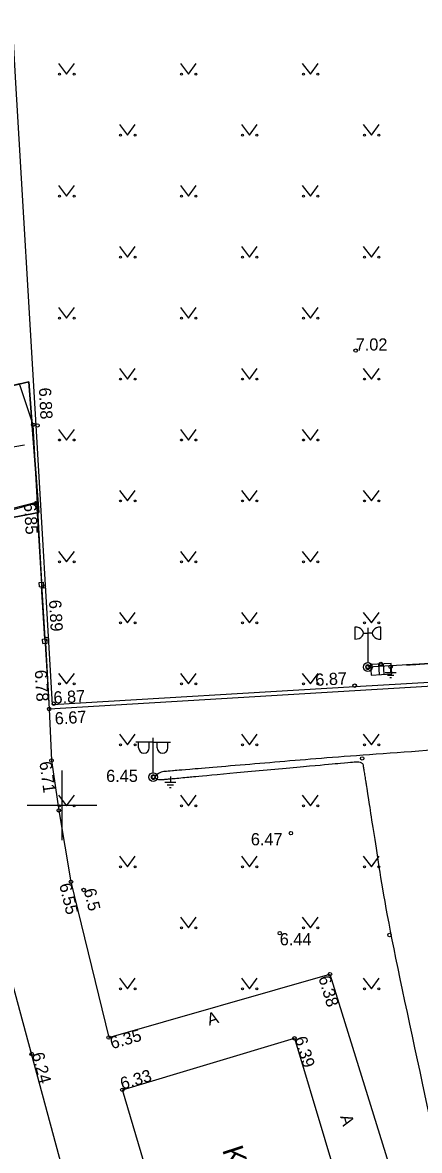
# Model space of a CAD drawing. Extents: x 473307 to 473719, y 6532843 to 6533381.
# Drawn here: x 473397.7 to 473420.5, y 6533180.2 to 6533244.9 of the extents above; entities that cross this region are included whole.
import ezdxf

# ---------------------------------------------------------------- set-up
doc = ezdxf.new("R2010")
doc.units = 0
for name, color, linetype in [('AED', 7, 'Continuous'), ('Default', 7, 'Continuous'), ('HALJASTUS', 7, 'Continuous'), ('HOONE', 7, 'Continuous'), ('KORGUS', 7, 'Continuous'), ('MPKAABEL', 7, 'Continuous'), ('PIIR', 7, 'Continuous'), ('POST', 7, 'Continuous'), ('RELJEEF', 7, 'Continuous'), ('TEE', 7, 'Continuous'), ('VORK', 7, 'Continuous')]:
    doc.layers.add(name, color=color, linetype=linetype)

# ---------------------------------------------------------------- blocks, each defined once
blk = doc.blocks.new('VARPOS')
at = {"layer": 'Default'}
for p, q in [((-0.25, 0.25), (-0.25, -0.25)), ((-0.25, 0.25), (0.25, 0.25)), ((0.25, 0.25), (0.25, -0.25)), ((-0.25, -0.25), (0.25, -0.25))]:
    blk.add_line(p, q, dxfattribs=at)
blk = doc.blocks.new('MEPOST')
at = {"layer": 'Default'}
blk.add_circle((0, 0), 0.5, dxfattribs=at)
for start, end in [(0, 180), (180, 0)]:
    blk.add_arc((0, 0), 0.25, start, end, dxfattribs=at)
blk = doc.blocks.new('VAPOS2')
at = {"layer": 'Default'}
for p, q in [((0, 4), (-2, 4)), ((-1.68, 3.36), (-1.68, 4)), ((-0.45, 3.36), (-0.45, 4)), ((0, 0.5), (0, 4.5)), ((0, 4), (2, 4)), ((0.45, 3.36), (0.45, 4)), ((1.68, 3.36), (1.68, 4))]:
    blk.add_line(p, q, dxfattribs=at)
for centre in [(-1.07, 3.36), (1.07, 3.36)]:
    blk.add_arc(centre, 0.613, 180, 0, dxfattribs=at)
blk = doc.blocks.new('ELKAPP')
at = {"layer": 'Default'}
for p, q in [((1.19, 0.6), (-1.19, 0.6)), ((-1.19, 0.6), (-1.19, -0.6)), ((-0.27, 0.6), (-0.27, -0.6)), ((0.27, 0.6), (0.27, -0.6)), ((1.19, -0.6), (1.19, 0.6)), ((-1.19, -0.6), (1.19, -0.6))]:
    blk.add_line(p, q, dxfattribs=at)
blk = doc.blocks.new('PRMAST')
at = {"layer": 'Default'}
for p, q in [((0, 4.5), (0, 0.5)), ((1.5, 3.19), (1.5, 4.59))]:
    blk.add_line(p, q, dxfattribs=at)
blk.add_lwpolyline([(0.5, 3.89), (0, 3.89)], dxfattribs=at)
blk.add_ellipse((1.5, 3.89), major_axis=(-1, 0), ratio=0.7, start_param=4.712389, end_param=7.853982, dxfattribs=at)
blk = doc.blocks.new('MAANDU')
at = {"layer": 'Default'}
for points in [[(0, 0), (0, -0.68)], [(0.64, -0.68), (-0.64, -0.68)], [(0.37, -0.98), (-0.37, -0.98)], [(0.1, -1.28), (-0.1, -1.28)]]:
    blk.add_lwpolyline(points, dxfattribs=at)
blk = doc.blocks.new('MURU')
at = {"layer": 'Default'}
for p, q in [((-0.93, 1.21), (0, 0)), ((0, 0), (0.89, 1.21))]:
    blk.add_line(p, q, dxfattribs=at)
for centre in [(-0.8, 0), (0.86, 0)]:
    blk.add_circle(centre, 0.11, dxfattribs=at)
blk = doc.blocks.new('VKORIS')
at = {"layer": 'Default'}
for p, q in [((0, 4), (0, -4)), ((-4, 0), (4, 0))]:
    blk.add_line(p, q, dxfattribs=at)

msp = doc.modelspace()

# ---------------------------------------------------------------- linework, layer by layer
at = {"layer": 'AED'}
for points in [[(473398.857, 6533212.804), (473398.35, 6533221.842), (473397.567, 6533224.199), (473383.137, 6533220.726)], [(473398.599, 6533217.405), (473385.116, 6533213.953)], [(473399.015, 6533209.548), (473398.836, 6533212.552)], [(473399.054, 6533209.3), (473399.274, 6533205.529), (473448.417, 6533208.478)]]:
    msp.add_lwpolyline(points, dxfattribs=at)
at = {"layer": 'HOONE'}
msp.add_lwpolyline([(473403.472, 6533183.664), (473413.359, 6533186.622), (473416.839, 6533174.996), (473406.945, 6533171.974), (473403.472, 6533183.664)], dxfattribs=at)
at = {"layer": 'KORGUS'}
for centre in [(473416.872, 6533226.101), (473398.35, 6533221.842), (473398.602, 6533221.804), (473398.54, 6533217.353), (473398.96, 6533212.559), (473399.14, 6533209.555), (473418.319, 6533208.108), (473417.57, 6533207.936), (473418.877, 6533207.948), (473416.817, 6533206.868), (473399.274, 6533205.529), (473399.534, 6533205.83), (473399.402, 6533202.567), (473417.242, 6533202.688), (473405.247, 6533201.618), (473399.824, 6533199.703), (473413.152, 6533198.4), (473400.522, 6533195.607), (473401.248, 6533195.139), (473412.511, 6533192.66), (473418.813, 6533192.552), (473415.393, 6533190.304), (473402.688, 6533186.668), (473413.359, 6533186.622), (473398.265, 6533185.719), (473403.472, 6533183.664)]:
    msp.add_circle(centre, 0.1, dxfattribs=at)
at = {"layer": 'MPKAABEL'}
for points in [[(473481.884, 6533211.687), (473479.589, 6533211.544), (473477.954, 6533211.443), (473473.664, 6533211.176), (473466.186, 6533210.711), (473462.033, 6533210.453), (473455.763, 6533210.064), (473450.004, 6533209.706), (473445.856, 6533209.448), (473442.754, 6533209.257), (473438.068, 6533209.011), (473432.416, 6533208.715), (473426.462, 6533208.402), (473419.78, 6533208.052), (473417.57, 6533207.936), (473481.884, 6533211.687), (473417.57, 6533207.936)], [(473557.128, 6533166.896), (473557.202, 6533167.153), (473557.17, 6533167.374), (473557.049, 6533167.727), (473556.952, 6533168.034), (473556.879, 6533168.251), (473556.724, 6533168.7), (473555.529, 6533172.103), (473554.018, 6533176.143), (473551.965, 6533180.794), (473542.001, 6533194.467), (473528.815, 6533203.479), (473521.877, 6533205.787), (473521.549, 6533205.862), (473521.332, 6533205.91), (473521.125, 6533205.955), (473520.94, 6533205.994), (473520.783, 6533206.026), (473520.617, 6533205.983), (473520.549, 6533205.81), (473520.512, 6533205.71), (473520.33, 6533205.301), (473520.277, 6533205.676), (473520.247, 6533205.87), (473520.186, 6533205.982), (473520.155, 6533206.063), (473520.032, 6533206.188), (473519.647, 6533206.25), (473519.297, 6533206.303), (473518.91, 6533206.37), (473518.338, 6533206.457), (473517.785, 6533206.534), (473517.113, 6533206.617), (473504.722, 6533206.361), (473489.125, 6533201.073), (473481.589, 6533195.708), (473477.331, 6533191.94), (473475.034, 6533189.807), (473474.489, 6533189.292), (473474.068, 6533188.932), (473473.832, 6533188.684), (473473.679, 6533188.468), (473473.566, 6533188.217), (473473.476, 6533188.304), (473473.306, 6533188.406), (473473.134, 6533188.531), (473472.969, 6533188.652), (473471.778, 6533189.567), (473469.957, 6533190.966), (473467.155, 6533193.119), (473463.064, 6533196.262), (473458.646, 6533199.657), (473454.573, 6533202.786), (473453.666, 6533203.482), (473453.293, 6533203.769), (473452.995, 6533203.998), (473452.474, 6533204.222), (473452.213, 6533204.228), (473451.967, 6533204.234), (473451.474, 6533204.245), (473450.255, 6533204.273), (473449.394, 6533204.293), (473448.978, 6533204.302), (473448.578, 6533204.312), (473448.301, 6533204.318), (473447.638, 6533204.311), (473446.313, 6533204.297), (473445.312, 6533204.286), (473443.932, 6533204.272), (473441.622, 6533204.247), (473436.282, 6533204.191), (473430.619, 6533203.804), (473423.016, 6533203.284), (473416.174, 6533202.8), (473411.7, 6533202.424), (473406.989, 6533202.027), (473406.298, 6533201.969), (473405.901, 6533201.936), (473405.663, 6533201.916), (473405.247, 6533201.618), (473405.511, 6533201.478), (473405.706, 6533201.471), (473405.859, 6533201.485), (473406.073, 6533201.505), (473406.3, 6533201.526), (473406.699, 6533201.563), (473407.182, 6533201.607), (473407.617, 6533201.647), (473410.794, 6533201.939), (473414.597, 6533202.289), (473416.16, 6533202.433), (473416.748, 6533202.487), (473416.992, 6533202.509), (473417.116, 6533202.479), (473417.282, 6533202.408), (473417.308, 6533202.242), (473417.347, 6533201.989), (473417.396, 6533201.677), (473417.449, 6533201.337), (473417.509, 6533200.949), (473418.04, 6533197.53), (473418.813, 6533192.552), (473421.708, 6533179.543), (473422.341, 6533175.512), (473423.507, 6533169.632), (473424, 6533167.141), (473424.184, 6533166.215), (473424.244, 6533165.909), (473424.294, 6533165.662), (473424.314, 6533165.561), (473424.105, 6533164.865), (473423.816, 6533164.809), (473423.525, 6533164.753), (473422.668, 6533164.588), (473418.846, 6533164.247), (473414.425, 6533164.061), (473411.47, 6533164.651), (473411.357, 6533164.673), (473410.881, 6533164.787), (473410.433, 6533164.888), (473409.953, 6533164.731), (473409.752, 6533164.287), (473409.631, 6533163.669), (473409.502, 6533157.703), (473410.074, 6533152.735), (473410.969, 6533148.729), (473415.098, 6533136.501), (473416.702, 6533131.364), (473421.711, 6533117.606), (473423.352, 6533113.701), (473430.005, 6533097.933), (473437.623, 6533088.588), (473441.02, 6533084.73), (473450.501, 6533069.242), (473457.775, 6533058.053), (473462.215, 6533052.558), (473465.73, 6533047.735), (473467.401, 6533046.054), (473469.034, 6533044.411), (473472.353, 6533043.145), (473481.411, 6533040.582), (473489.023, 6533038.632), (473491.007, 6533038.103), (473491.686, 6533037.936), (473492.014, 6533037.852), (473492.476, 6533037.76), (473492.806, 6533038.095), (473492.829, 6533038.485), (473492.856, 6533039.18), (473492.795, 6533042.335), (473492.716, 6533044.024), (473492.683, 6533044.743), (473492.671, 6533044.987), (473492.823, 6533045.601), (473492.984, 6533045.289), (473492.985, 6533045.105), (473493.028, 6533044.585), (473493.105, 6533042.767), (473493.222, 6533039.506), (473493.206, 6533038.15), (473493.196, 6533038.01), (473493.2, 6533037.815), (473493.516, 6533037.437), (473493.94, 6533037.314), (473494.338, 6533037.204), (473496.451, 6533036.58), (473497.497, 6533036.067), (473498.11, 6533035.695), (473498.481, 6533035.454), (473498.784, 6533035.294), (473499.155, 6533035.524), (473499.568, 6533035.786), (473499.965, 6533035.642), (473500.381, 6533035.468), (473500.664, 6533035.366), (473501.255, 6533035.156), (473502.131, 6533034.826), (473503.015, 6533034.496), (473504.909, 6533033.785), (473507.281, 6533033.099), (473509.703, 6533032.392), (473510.465, 6533032.171), (473510.886, 6533032.05), (473511.297, 6533031.932), (473511.665, 6533031.668), (473511.711, 6533031.312), (473511.692, 6533030.835), (473511.632, 6533029.982), (473511.533, 6533028.937), (473511.486, 6533028.283), (473511.407, 6533027.141), (473511.358, 6533026.503), (473511.358, 6533025.257), (473511.617, 6533023.934), (473511.536, 6533023.5), (473511.414, 6533022.901), (473511.43, 6533022.205), (473511.677, 6533020.728), (473511.888, 6533019.916), (473512.37, 6533017.914), (473512.52, 6533015.831), (473512.626, 6533013.709), (473512.595, 6533013.242), (473512.387, 6533012.718), (473557.128, 6533166.896), (473512.387, 6533012.718)]]:
    msp.add_open_spline(points, degree=3, dxfattribs=at)
at = {"layer": 'PIIR'}
for points in [[(473383.26, 6533220.83), (473372.23, 6533259.41), (473496.37, 6533266.79), (473499.84, 6533206.38), (473559.2, 6533209.37), (473561.43, 6533165.2), (473601.75, 6533167.04), (473607.56, 6533132.38), (473611.09, 6533109.85), (473618.6, 6533063.82), (473572.63, 6533056.43), (473548.5, 6533028.91), (473478.82, 6533017), (473455.33, 6533045.76), (473432.18, 6533083.36), (473429.59, 6533087.74), (473409.64, 6533129), (473385.1, 6533214.25), (473398.68, 6533216.8), (473398.11, 6533224.3)], [(473383.26, 6533220.83), (473398.11, 6533224.3), (473398.68, 6533216.8), (473385.1, 6533214.25)]]:
    msp.add_lwpolyline(points, close=True, dxfattribs=at)
at = {"layer": 'POST'}
msp.add_line((473416.82, 6533210.232), (473416.82, 6533209.532), dxfattribs=at)
msp.add_lwpolyline([(473417.32, 6533209.882), (473417.57, 6533209.882)], dxfattribs=at)
msp.add_ellipse((473416.82, 6533209.882), major_axis=(0.5, 0), ratio=0.7, start_param=4.712389, end_param=7.853982, dxfattribs=at)
at = {"layer": 'RELJEEF'}
msp.add_line((473396.049, 6533220.39), (473397.858, 6533220.686), dxfattribs=at)
at = {"layer": 'TEE'}
msp.add_lwpolyline([(473396.254, 6533260.803), (473411.137, 6533261.686), (473430.688, 6533262.81), (473450.64, 6533263.99), (473471.14, 6533265.187), (473496.199, 6533266.651), (473497.903, 6533237.901), (473499.304, 6533214.158), (473499.292, 6533213.775), (473499.248, 6533213.313), (473499.158, 6533212.95), (473498.962, 6533212.533), (473498.665, 6533212.147), (473498.271, 6533211.83), (473497.797, 6533211.622), (473497.201, 6533211.492), (473496.826, 6533211.447), (473473.837, 6533210.118), (473452.83, 6533208.91), (473434.945, 6533207.846), (473416.821, 6533206.798), (473399.468, 6533205.756), (473398.532, 6533221.8), (473397.351, 6533241.472)], close=True, dxfattribs=at)
msp.add_lwpolyline([(473400.457, 6533177.573), (473397, 6533190.419), (473394.101, 6533202.257), (473393.903, 6533202.637), (473393.566, 6533203.083), (473393.27, 6533203.363), (473392.905, 6533203.62), (473392.434, 6533203.847), (473391.828, 6533204.003), (473391.19, 6533204.027), (473388.768, 6533203.46), (473386.852, 6533210.309), (473391.608, 6533211.678), (473390.864, 6533215.166), (473398.54, 6533217.353), (473399.274, 6533205.529), (473399.402, 6533202.567), (473399.824, 6533199.703), (473400.522, 6533195.607), (473402.688, 6533186.668), (473415.393, 6533190.304), (473419.893, 6533175.809)], dxfattribs=at)

# ---------------------------------------------------------------- block references
at = {"layer": 'AED', "xscale": 0.5, "yscale": 0.5000000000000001, "rotation": 93.41886921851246}
for p in [(473398.828, 6533212.677), (473398.828, 6533212.677), (473399.023, 6533209.423), (473399.023, 6533209.423)]:
    msp.add_blockref('VARPOS', p, dxfattribs=at)
at = {"layer": 'HALJASTUS', "xscale": 0.5, "yscale": 0.5}
for p in [(473400.271, 6533241.967), (473407.271, 6533241.967), (473414.271, 6533241.967), (473403.771, 6533238.467), (473410.771, 6533238.467), (473417.771, 6533238.467), (473400.271, 6533234.967), (473407.271, 6533234.967), (473414.271, 6533234.967), (473403.771, 6533231.467), (473410.771, 6533231.467), (473417.771, 6533231.467), (473400.271, 6533227.967), (473407.271, 6533227.967), (473414.271, 6533227.967), (473403.771, 6533224.467), (473410.771, 6533224.467), (473417.771, 6533224.467), (473400.271, 6533220.967), (473407.271, 6533220.967), (473414.271, 6533220.967), (473403.771, 6533217.467), (473410.771, 6533217.467), (473417.771, 6533217.467), (473400.271, 6533213.967), (473407.271, 6533213.967), (473414.271, 6533213.967), (473403.771, 6533210.467), (473410.771, 6533210.467), (473417.771, 6533210.467), (473400.271, 6533206.967), (473407.271, 6533206.967), (473414.271, 6533206.967), (473403.771, 6533203.467), (473410.771, 6533203.467), (473417.771, 6533203.467), (473400.271, 6533199.967), (473407.271, 6533199.967), (473414.271, 6533199.967), (473403.771, 6533196.467), (473410.771, 6533196.467), (473417.771, 6533196.467), (473407.271, 6533192.967), (473414.271, 6533192.967), (473403.771, 6533189.467), (473410.771, 6533189.467), (473417.771, 6533189.467)]:
    msp.add_blockref('MURU', p, dxfattribs=at)
at = {"layer": 'MPKAABEL', "xscale": 0.5, "yscale": 0.5}
for p in [(473418.877, 6533207.948), (473406.229, 6533201.644)]:
    msp.add_blockref('MAANDU', p, dxfattribs=at)
at = {"layer": 'POST'}
for name, p, xscale, yscale in [('PRMAST', (473417.57, 6533207.936), 0.4999999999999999, 0.4999999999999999), ('MEPOST', (473417.57, 6533207.936), 0.4999999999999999, 0.4999999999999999), ('VAPOS2', (473405.247, 6533201.618), 0.5, 0.5), ('MEPOST', (473405.247, 6533201.618), 0.5, 0.5)]:
    msp.add_blockref(name, p, dxfattribs=dict(at, xscale=xscale, yscale=yscale))
at = {"layer": 'POST', "xscale": 0.5000000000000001, "yscale": 0.4999999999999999, "rotation": 3.29035056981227}
msp.add_blockref('ELKAPP', (473418.336, 6533207.81), dxfattribs=at)
at = {"layer": 'VORK', "xscale": 0.5, "yscale": 0.5}
msp.add_blockref('VKORIS', (473400, 6533200), dxfattribs=at)

# ---------------------------------------------------------------- texts
at = {"layer": 'HOONE'}
msp.add_text('KK', height=1.2, rotation=288.01495, dxfattribs=at).set_placement((473409.194, 6533180.224))
at = {"layer": 'KORGUS'}
for s, p in [('7.02', (473416.872, 6533226.101)), ('6.45', (473402.542, 6533201.339)), ('6.47', (473410.852, 6533197.7)), ('6.44', (473412.511, 6533191.96))]:
    msp.add_text(s, height=0.7, dxfattribs=at).set_placement(p)
for s, rotation, p in [('6.88', 273, (473398.68, 6533223.958)), ('6.85', 273.55314, (473397.817, 6533217.34)), ('6.89', 273.21221, (473399.261, 6533211.776)), ('6.78', 273.3405, (473398.443, 6533207.752)), ('6.87', 3, (473414.569, 6533206.85)), ('6.87', 3, (473399.534, 6533205.83)), ('6.67', 3.38911, (473399.61, 6533204.631)), ('6.71', 277.69348, (473398.708, 6533202.474)), ('6.55', 283.62095, (473399.842, 6533195.442)), ('6.5', 283.62095, (473401.248, 6533195.139)), ('6.38', 286.79978, (473414.723, 6533190.102)), ('6.35', 15.96821, (473402.881, 6533185.995)), ('6.39', 286.6673, (473413.359, 6533186.622)), ('6.24', 285.06452, (473398.265, 6533185.719)), ('6.33', 16.6673, (473403.472, 6533183.664))]:
    msp.add_text(s, height=0.7, rotation=rotation, dxfattribs=at).set_placement(p)
at = {"layer": 'TEE'}
for rotation, p in [(16.6673, (473408.458, 6533187.344)), (286.79978, (473415.966, 6533182.128))]:
    msp.add_text('A', height=0.7, rotation=rotation, dxfattribs=at).set_placement(p)

doc.saveas('drawing.dxf')
